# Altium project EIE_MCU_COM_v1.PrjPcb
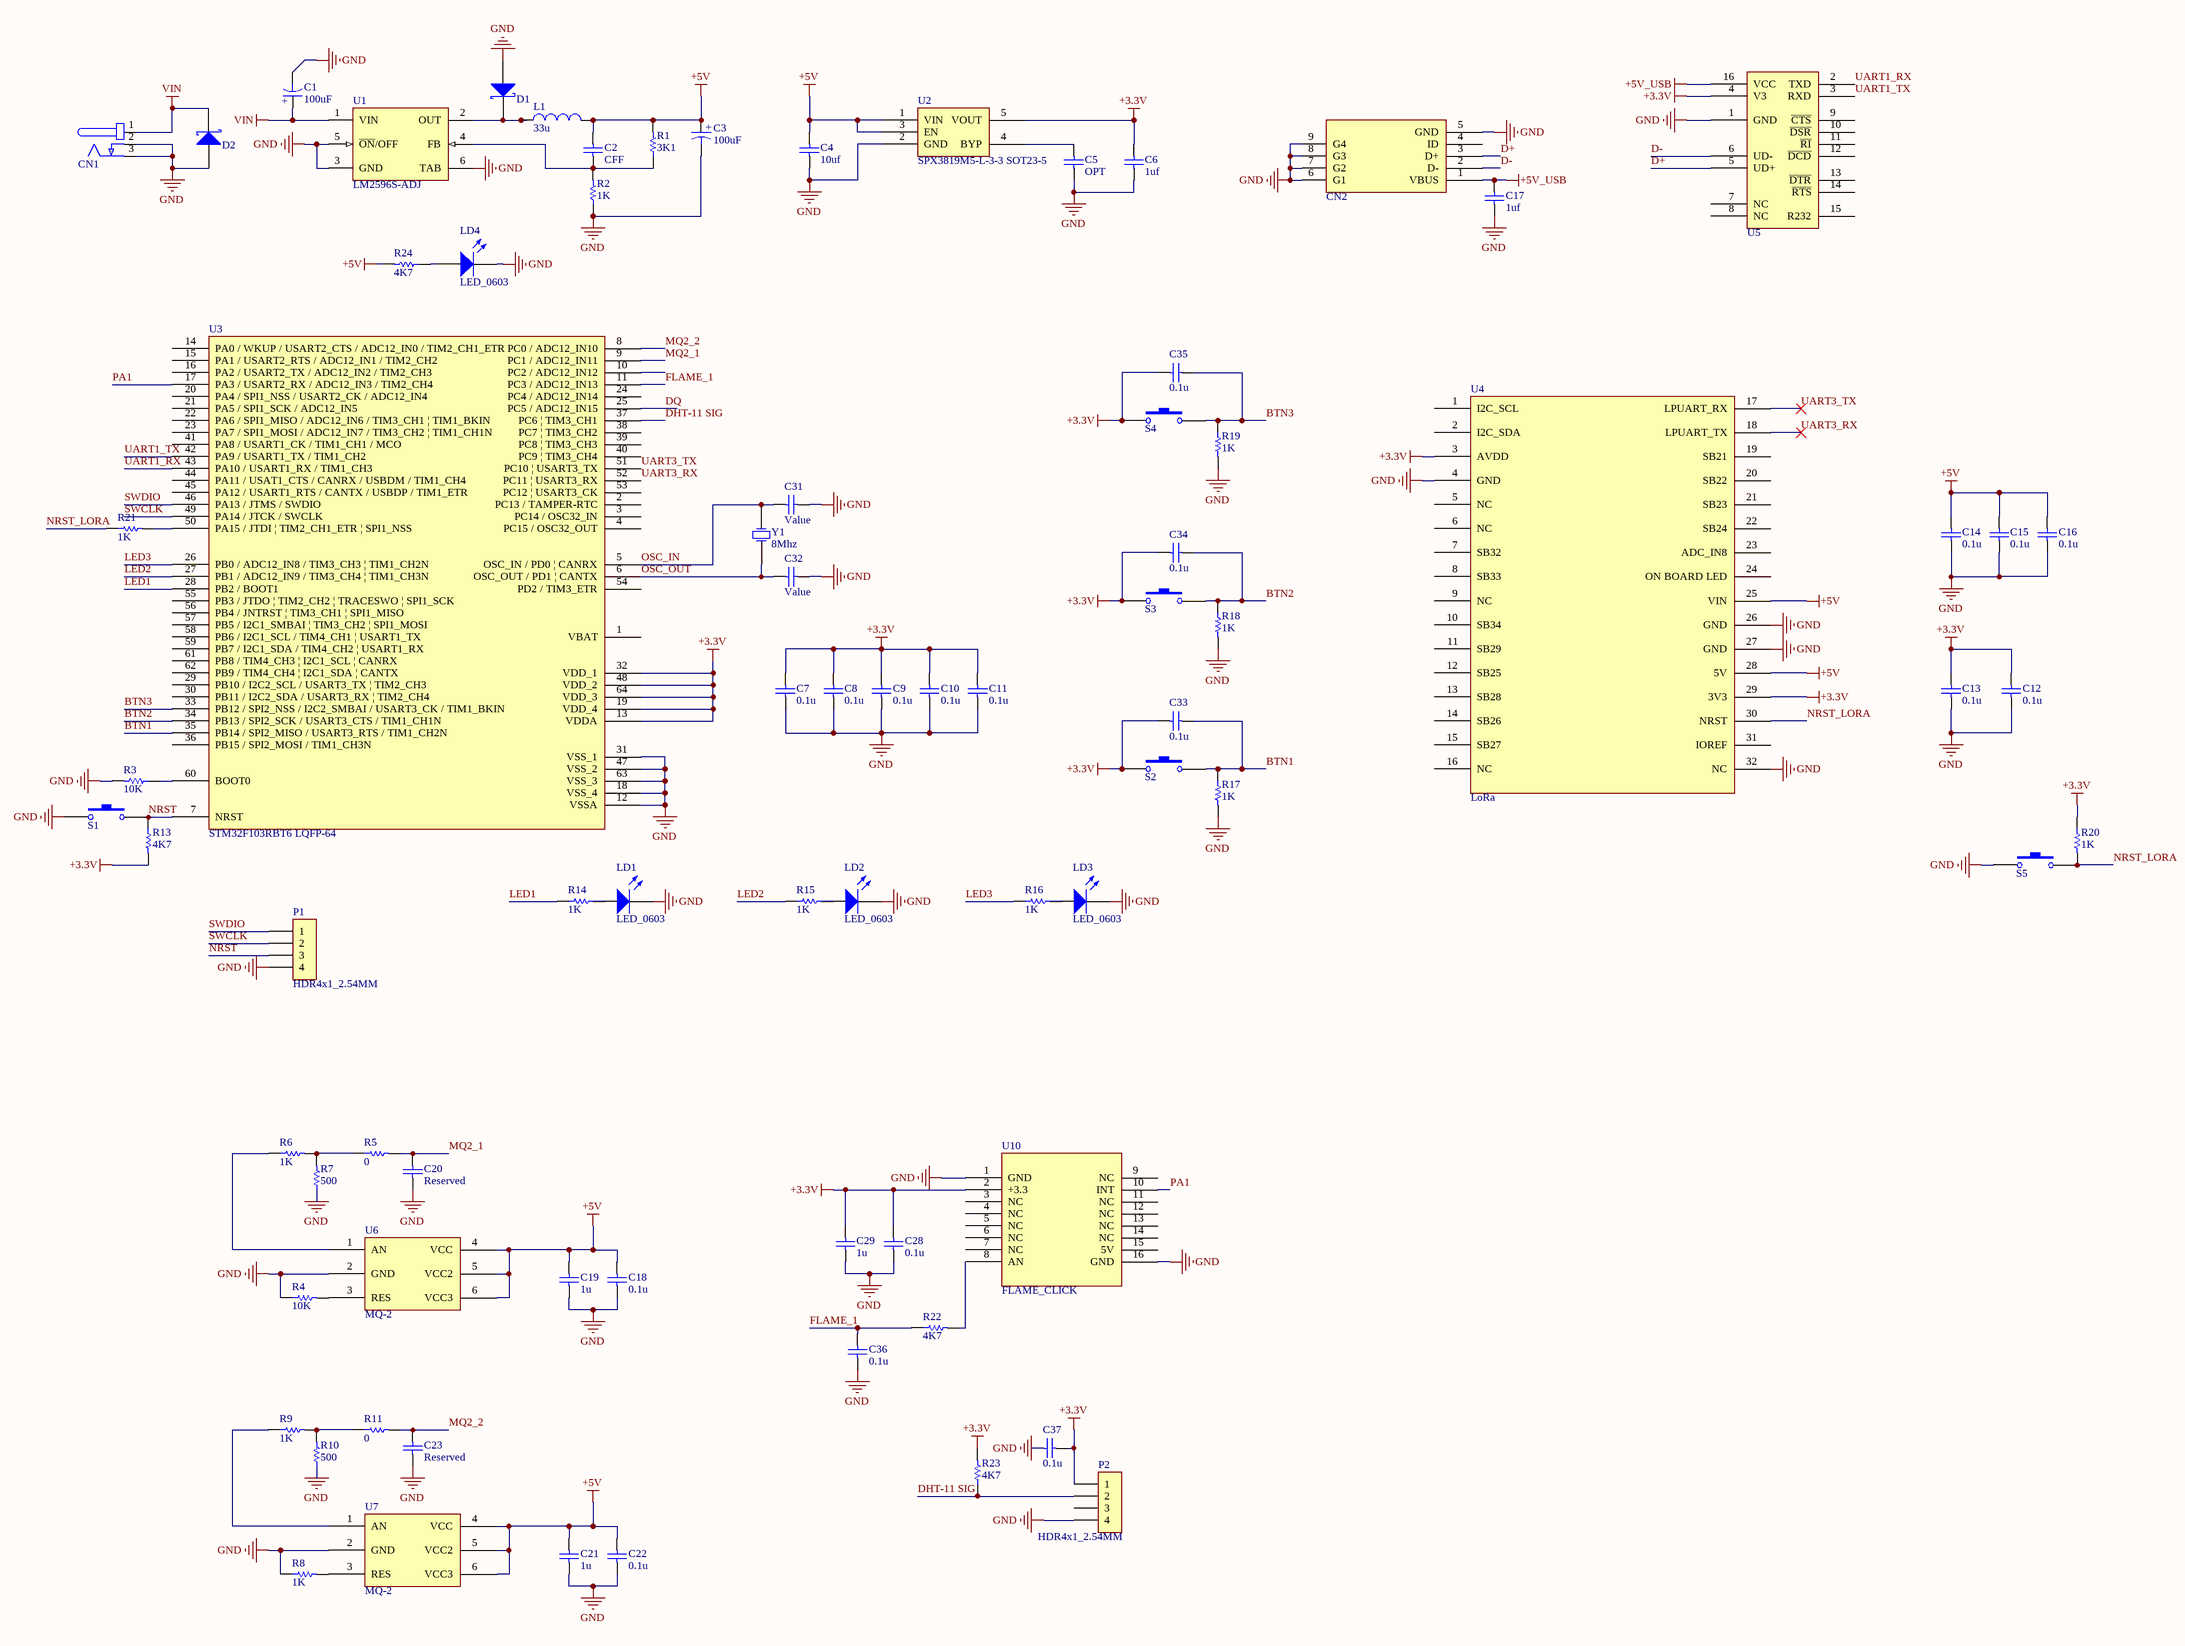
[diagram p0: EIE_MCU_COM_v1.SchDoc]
1 sheet, 80 parts. Net scope: global (net labels, ports and power ports of the same name join across sheets).

## Sheet EIE_MCU_COM_v1.SchDoc
size A2

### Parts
C1  100uF  [E-CAP_D8.2X16_LS3.2]
C2  CFF  [CAP_0603_SMD]
C3  100uF  [E-CAP_D8.2X16_LS3.2]
C4  10uf  [CAP_1206_SMD]
C5  OPT  [CAP_0603_SMD]
C6  1uf  [CAP_0603_SMD]
C7  0.1u  [CAP_0603_SMD]
C8  0.1u  [CAP_0603_SMD]
C9  0.1u  [CAP_0603_SMD]
C10  0.1u  [CAP_0603_SMD]
C11  0.1u  [CAP_0603_SMD]
C12  0.1u  [CAP_0603_SMD]
C13  0.1u  [CAP_0603_SMD]
C14  0.1u  [CAP_0603_SMD]
C15  0.1u  [CAP_0603_SMD]
C16  0.1u  [CAP_0603_SMD]
C17  1uf  [CAP_0603_SMD]
C18  0.1u  [CAP_0603_SMD]
C19  1u  [CAP_0603_SMD]
C20  Reserved  [CAP_0603_SMD]
C21  1u  [CAP_0603_SMD]
C22  0.1u  [CAP_0603_SMD]
C23  Reserved  [CAP_0603_SMD]
C28  0.1u  [CAP_0603_SMD]
C29  1u  [CAP_0603_SMD]
C31  Value  [CAP_0603_SMD]
C32  Value  [CAP_0603_SMD]
C33  0.1u  [CAP_0603_SMD]
C34  0.1u  [CAP_0603_SMD]
C35  0.1u  [CAP_0603_SMD]
C36  0.1u  [CAP_0603_SMD]
C37  0.1u  [CAP_0603_SMD]
CN1  PWR5.5x2.1  [PWR5.5x2.1]  (value not drawn)
CN2  MiniUSB Socket SMT  [MiniUSB Socket SMT]  (value not drawn)
D1  SS34_A  [1N5822 SS34 Type_A SMT]  (value not drawn)
D2  SS34_A  [1N5822 SS34 Type_A SMT]  (value not drawn)
L1  33u  [IND_CDRH104R_10MM]
LD1  LED_0603  [LED_0603]
LD2  LED_0603  [LED_0603]
LD3  LED_0603  [LED_0603]
LD4  LED_0603  [LED_0603]
P1  HDR4x1_2.54MM  [HDR4x1_2.54]
P2  HDR4x1_2.54MM  [HDR4x1_2.54]
R1  3K1  [RES_0603_SMD]
R2  1K  [RES_0603_SMD]
R3  10K  [RES_0603_SMD]
R4  10K  [RES_0603_SMD]
R5  0  [RES_0603_SMD]
R6  1K  [RES_0603_SMD]
R7  500  [RES_0603_SMD]
R8  1K  [RES_0603_SMD]
R9  1K  [RES_0603_SMD]
R10  500  [RES_0603_SMD]
R11  0  [RES_0603_SMD]
R13  4K7  [RES_0603_SMD]
R14  1K  [RES_0603_SMD]
R15  1K  [RES_0603_SMD]
R16  1K  [RES_0603_SMD]
R17  1K  [RES_0603_SMD]
R18  1K  [RES_0603_SMD]
R19  1K  [RES_0603_SMD]
R20  1K  [RES_0603_SMD]
R21  1K  [RES_0603_SMD]
R22  4K7  [RES_0603_SMD]
R23  4K7  [RES_0603_SMD]
R24  4K7  [RES_0603_SMD]
S1  PBTN_SMD_6x6x5_4P_BK  [PBTN_SMD_6x6x5_4P_BK]  (value not drawn)
S2  PBTN_SMD_6x6x5_4P_BK  [PBTN_SMD_6x6x5_4P_BK]  (value not drawn)
S3  PBTN_SMD_6x6x5_4P_BK  [PBTN_SMD_6x6x5_4P_BK]  (value not drawn)
S4  PBTN_SMD_6x6x5_4P_BK  [PBTN_SMD_6x6x5_4P_BK]  (value not drawn)
S5  PBTN_SMD_6x6x5_4P_BK  [PBTN_SMD_6x6x5_4P_BK]  (value not drawn)
U1  LM2596S-ADJ  [LM2596S]
U2  SPX3819M5-L-3-3 SOT23-5  [IC_SOT23-5]
U3  STM32F103RBT6 LQFP-64  [IC_LQFP-64]
U4  LoRa  [ST LoRa externsion]
U5  CH340C SOP-16  [IC_SOP-16]  (value not drawn)
U6  MQ-2  [PCBComponent_1]
U7  MQ-2  [PCBComponent_1]
U10  FLAME_CLICK  [PCBComponent_1]
Y1  8Mhz  [XTAL_SMD]

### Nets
+3.3V: C6.2 C7.2 C8.2 C9.2 C10.2 C11.2 C12.2 C13.2 C28.2 C29.2 C33.2 C34.2 C35.2 C37.2 P2.1 R13.2 R20.1 R23.2 S2.1 S3.1 S4.1 U2.5(VOUT) U3.13(VDDA) U3.19(VDD_4) U3.32(VDD_1) U3.48(VDD_2) U3.64(VDD_3) U4.3(AVDD) U4.29(3V3) U5.4(V3) U10.2(+3.3)
+5V: C2.2 C3.1(+) C4.2 C14.2 C15.2 C16.2 C18.2 C19.2 C21.2 C22.2 L1.2 R1.2 R24.2 U2.1(VIN) U2.3(EN) U4.25(VIN) U4.28(5V) U6.4(VCC) U6.5(VCC2) U6.6(VCC3) U7.4(VCC) U7.5(VCC2) U7.6(VCC3)
+5V_USB: C17.2 CN2.1(VBUS) U5.16(VCC)
GND: C1.2(-) C3.2(-) C4.1 C5.1 C6.1 C7.1 C8.1 C9.1 C10.1 C11.1 C12.1 C13.1 C14.1 C15.1 C16.1 C17.1 C18.1 C19.1 C20.1 C21.1 C22.1 C23.1 C28.1 C29.1 C31.1 C32.1 C36.1 C37.1 CN1.2(GND) CN1.3(GND) CN2.5(GND) CN2.6(G1) CN2.7(G2) CN2.8(G3) CN2.9(G4) D1.1(A) D2.1(A) LD1.2(K) LD2.2(K) LD3.2(K) LD4.2(K) P1.4 P2.4 R2.1 R3.2 R4.1 R7.1 R8.1 R10.1 R17.2 R18.2 R19.2 S1.1 S5.1 U1.3(GND) U1.5(~{ON}/OFF) U1.6(TAB) U2.2(GND) U3.12(VSSA) U3.18(VSS_4) U3.31(VSS_1) U3.47(VSS_2) U3.63(VSS_3) U4.4(GND) U4.26(GND) U4.27(GND) U4.32(NC) U5.1(GND) U6.2(GND) U7.2(GND) U10.1(GND) U10.16(GND)
VIN: C1.1(+) CN1.1(+) D2.2(K) U1.1(VIN)
BTN1: C33.1 R17.1 S2.2 U3.35(PB14_/_SPI2_MISO_/_USART3_RTS_/_TIM1_CH2N)
BTN2: C34.1 R18.1 S3.2 U3.34(PB13_/_SPI2_SCK_/_USART3_CTS_/_TIM1_CH1N)
BTN3: C35.1 R19.1 S4.2 U3.33(PB12_/_SPI2_NSS_/_I2C2_SMBAI_/_USART3_CK_/_TIM1_BKIN)
D+: CN2.3(D+) U5.5(UD+)
D-: CN2.2(D-) U5.6(UD-)
DHT-11 SIG: P2.2 R23.1 U3.37(PC6_¦_TIM3_CH1)
DQ: U3.25(PC5_/_ADC12_IN15)
FLAME_1: C36.2 R22.1 U3.11(PC3_/_ADC12_IN13)
LED1: R14.1 U3.28(PB2_/_BOOT1)
LED2: R15.1 U3.27(PB1_/_ADC12_IN9_/_TIM3_CH4_¦_TIM1_CH3N)
LED3: R16.1 U3.26(PB0_/_ADC12_IN8_/_TIM3_CH3_¦_TIM1_CH2N)
MQ2_1: C20.2 R5.2 U3.9(PC1_/_ADC12_IN11)
MQ2_2: C23.2 R11.2 U3.8(PC0_/_ADC12_IN10)
NRST: P1.3 R13.1 S1.2 U3.7(NRST)
NRST_LORA: R20.2 R21.1 S5.2 U4.30(NRST)
OSC_IN: C31.2 U3.5(OSC_IN_/_PD0_¦_CANRX) Y1.2(OSC2)
OSC_OUT: C32.2 U3.6(OSC_OUT_/_PD1_¦_CANTX) Y1.1(OSC1)
PA1: U3.17(PA3_/_USART2_RX_/_ADC12_IN3_/_TIM2_CH4) U10.10(INT)
SWCLK: P1.2 U3.49(PA14_/_JTCK_/_SWCLK)
SWDIO: P1.1 U3.46(PA13_/_JTMS_/_SWDIO)
UART1_RX: U3.43(PA10_/_USART1_RX_/_TIM1_CH3) U5.2(TXD)
UART1_TX: U3.42(PA9_/_USART1_TX_/_TIM1_CH2) U5.3(RXD)
UART3_RX: U3.52(PC11_¦_USART3_RX) U4.18(LPUART_TX)
UART3_TX: U3.51(PC10_¦_USART3_TX) U4.17(LPUART_RX)
NetC2_1: C2.1 R1.1 R2.2 U1.4(FB)
NetC5_2: C5.2 U2.4(BYP)
NetD1_2: D1.2(K) L1.1 U1.2(OUT)
NetLD1_1: LD1.1(A) R14.2
NetLD2_1: LD2.1(A) R15.2
NetLD3_1: LD3.1(A) R16.2
NetLD4_1: LD4.1(A) R24.1
NetR3_1: R3.1 U3.60(BOOT0)
NetR4_2: R4.2 U6.3(RES)
NetR5_1: R5.1 R6.2 R7.2
NetR6_1: R6.1 U6.1(AN)
NetR8_2: R8.2 U7.3(RES)
NetR9_1: R9.1 U7.1(AN)
NetR9_2: R9.2 R10.2 R11.1
NetR21_2: R21.2 U3.50(PA15_/_JTDI_¦_TIM2_CH1_ETR_¦_SPI1_NSS)
NetR22_2: R22.2 U10.8(AN)

Not connected (* = marked no-connect by the designer): CN2 4(ID); P2 3; U3 1(VBAT) 2(PC13_/_TAMPER-RTC) 3(PC14_/_OSC32_IN) 4(PC15_/_OSC32_OUT) 10(PC2_/_ADC12_IN12) 14(PA0_/_WKUP_/_USART2_CTS_/_ADC12_IN0_/_TIM2_CH1_ETR) 15(PA1_/_USART2_RTS_/_ADC12_IN1_/_TIM2_CH2) 16(PA2_/_USART2_TX_/_ADC12_IN2_/_TIM2_CH3) 20(PA4_/_SPI1_NSS_/_USART2_CK_/_ADC12_IN4) 21(PA5_/_SPI1_SCK_/_ADC12_IN5) 22(PA6_/_SPI1_MISO_/_ADC12_IN6_/_TIM3_CH1_¦_TIM1_BKIN) 23(PA7_/_SPI1_MOSI_/_ADC12_IN7_/_TIM3_CH2_¦_TIM1_CH1N) 24(PC4_/_ADC12_IN14) 29(PB10_/_I2C2_SCL_/_USART3_TX_¦_TIM2_CH3) 30(PB11_/_I2C2_SDA_/_USART3_RX_¦_TIM2_CH4) 36(PB15_/_SPI2_MOSI_/_TIM1_CH3N) 38(PC7_¦_TIM3_CH2) 39(PC8_¦_TIM3_CH3) 40(PC9_¦_TIM3_CH4) 41(PA8_/_USART1_CK_/_TIM1_CH1_/_MCO) 44(PA11_/_USAT1_CTS_/_CANRX_/_USBDM_/_TIM1_CH4) 45(PA12_/_USART1_RTS_/_CANTX_/_USBDP_/_TIM1_ETR) 53(PC12_¦_USART3_CK) 54(PD2_/_TIM3_ETR) 55(PB3_/_JTDO_¦_TIM2_CH2_¦_TRACESWO_¦_SPI1_SCK) 56(PB4_/_JNTRST_¦_TIM3_CH1_¦_SPI1_MISO) 57(PB5_/_I2C1_SMBAI_¦_TIM3_CH2_¦_SPI1_MOSI) 58(PB6_/_I2C1_SCL_/_TIM4_CH1_¦_USART1_TX) 59(PB7_/_I2C1_SDA_/_TIM4_CH2_¦_USART1_RX) 61(PB8_/_TIM4_CH3_¦_I2C1_SCL_¦_CANRX) 62(PB9_/_TIM4_CH4_¦_I2C1_SDA_¦_CANTX); U4 1(I2C_SCL) 2(I2C_SDA) 5(NC) 6(NC) 7(SB32) 8(SB33) 9(NC) 10(SB34) 11(SB29) 12(SB25) 13(SB28) 14(SB26) 15(SB27) 16(NC) 19(SB21) 20(SB22) 21(SB23) 22(SB24) 23(ADC_IN8) 24(ON_BOARD_LED) 31(IOREF); U5 7(NC) 8(NC) 9(~{CTS}) 10(~{DSR}) 11(~{RI}) 12(~{DCD}) 13(~{DTR}) 14(~{RTS}) 15(R232); U10 3(NC) 4(NC) 5(NC) 6(NC) 7(NC) 9(NC) 11(NC) 12(NC) 13(NC) 14(NC) 15(5V)

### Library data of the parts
C1 C3 = E-CAP_D8.2X16_LS3.2
C2 C5-C23 C28 C29 C31-C37 = CAP_0603_SMD: Capacitor, 0603, SMD
C4 = CAP_1206_SMD: Capacitor, 1206, SMD
CN1 = PWR5.5x2.1: DC Socket, 5.5x2.1
CN2 = MiniUSB Socket SMT: MicroUSB Socket, SMT
D1 D2 = 1N5822 SS34 Type_A SMT
L1 = IND_CDRH104R_10MM: Inductor, CDRH104R, 10MM; Code_IEC: 1005
LD1-LD4 = LED_0603: LED 0603
P1 P2 = HDR4x1_2.54: Header, 4-Pin, 1-Row, 2.54mm Pitch
R1-R11 R13-R24 = RES_0603_SMD: Resistor, 0603, SMD
S1-S5 = PBTN_SMD_6x6x5_4P_BK: Switch
U1 = LM2596S-ADJ: SIMPLE SWITCHER Power Converter 150 KHz 3A Step-Down Voltage Regulator; Manufacturer: National Semiconductor; PackageTopMarking: NSUZXYTT*LM2596S*-ADJ P+; PowerWise: N
U2 = SPX3819M5-L-3-3 SOT23-5: VREG, 3.3V, 500mA
U3 = STM32F103RBT6 LQFP-64: STM32 ARM-based 32-bit MCU with 128 Kbytes Flash, 64-pin LQFP, Industrial Temperature
U4 U6 U7 U10 = Component_1
U5 = CH340C SOP-16: USB to Serial Chip
Y1 = XTAL_SMD: Crystal Oscillator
